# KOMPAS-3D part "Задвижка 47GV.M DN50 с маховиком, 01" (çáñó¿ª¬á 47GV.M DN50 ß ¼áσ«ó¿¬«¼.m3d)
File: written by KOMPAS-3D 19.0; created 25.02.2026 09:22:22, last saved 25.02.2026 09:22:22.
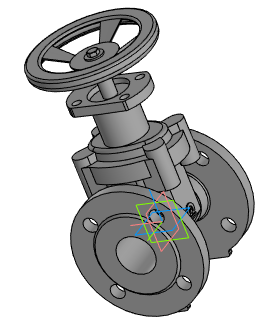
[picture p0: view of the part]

Document properties: Автор: Евгений; Полное имя файла: 47 GV.M DN50\Задвижка 47GV.M DN50 с маховиком.a3d

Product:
- Part/product: Задвижка 47GV.M DN50 с маховиком  | designation 01
    Масса: 10.055
  - Component [detail]: Корпус  | pos. 3  | Материал: ВЧ50 ГОСТ 7293-85 (density 7200 kg/m3); Масса: 8.77519; Раздел спецификации: Детали; Форматы листов документа: 2xA3; source file: 47 GV.M DN50\DR.47GVM.050.16.00.001 - Корпус.cdw, 47 GV.M DN50\Корпус 47GV.M DN50.m3d
  - Component [assembly]: Клин с направляющими  | designation DR.47GVM.050.16.01.000  | pos. 4  | Раздел спецификации: Сборочные единицы; Форматы листов документа: A4; source file: 47 GV.M DN50\DR.47GVM.050.16.01.000  - Клин с направляющими.a3d, 47 GV.M DN50\DR.47GVM.050.16.01.000  - Клин с направляющими.spw, 47 GV.M DN50\DR.47GVM.050.16.01.000  СБ - Клин с направляющими.cdw
  - Component [detail]: Крышка  | pos. 4  | Материал: ВЧ50 ГОСТ 7293-85 (density 7200 kg/m3); Масса: 2.87085; Раздел спецификации: Детали; source file: 47 GV.M DN50\DR.47GVM.050.16.00.002 - Крышка.cdw, 47 GV.M DN50\Крышка 47GV.M DN50.m3d
  - Component [detail]: Шпиндель  | pos. 5  | Материал: Сталь 20Х13 ГОСТ 5632-2014 (density 7670 kg/m3); Масса: 0.101759; Раздел спецификации: Детали; source file: 47 GV.M DN50\DR.47GVM.050.16.00.003 - Шпиндель.cdw, 47 GV.M DN50\Шпиндель 47GV.M DN50.m3d
  - Component [detail]: Маховик 160  | pos. 19  | Масса: 0.340724; Раздел спецификации: Прочие изделия; source file: 47 GV.M DN50\Маховик 160.m3d
  - Component [standard]: Шайба821695878  | pos. 16
      Материал: Сталь 12Х18Н10Т ГОСТ 5632-2014 (density 1000 kg/m3)
      Масса: 0.000793943
      Раздел спецификации: Стандартные изделия
      Примечание: См. п.6 ТТ
      Рассекать на разрезах: no
      additional columns: ГОСТ 6958-78; A 8.21
  - Component [standard]: Болт86g187798  | pos. 17  | Масса: 0.0123; Раздел спецификации: Стандартные изделия; Примечание: См. п.6 ТТ; Рассекать на разрезах: no; additional columns: ГОСТ 7798-70; М8-6gx18
- Part/product: Задвижка 47GV.M DN50 с маховиком
    Масса: 12.1071
    Раздел спецификации: Документация
    Форматы листов документа: 2xA3
    source file: 47 GV.M DN50\DR.47GVM.050.16.00.000 - Задвижка с обрезиненным клином DN50.spw, 47 GV.M DN50\DR.47GVM.050.16.00.000 СБ - Задвижка с обрезиненным клином DN100.cdw
  - Component: Задвижка с обрезиненным клином DN50. Сборочный чертеж  | designation DR.47GVM.050.16.00.000СБ  | pos. 0  | Масса: 10.0548; Раздел спецификации: Документация; Форматы листов документа: 2xA3; source file: 47 GV.M DN50\DR.47GVM.050.16.00.000 СБ - Задвижка с обрезиненным клином DN100.cdw

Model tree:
1. Операция без истории:1

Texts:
  Точка начала. Х
  Точка начала. Y
  Точка начала. Z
